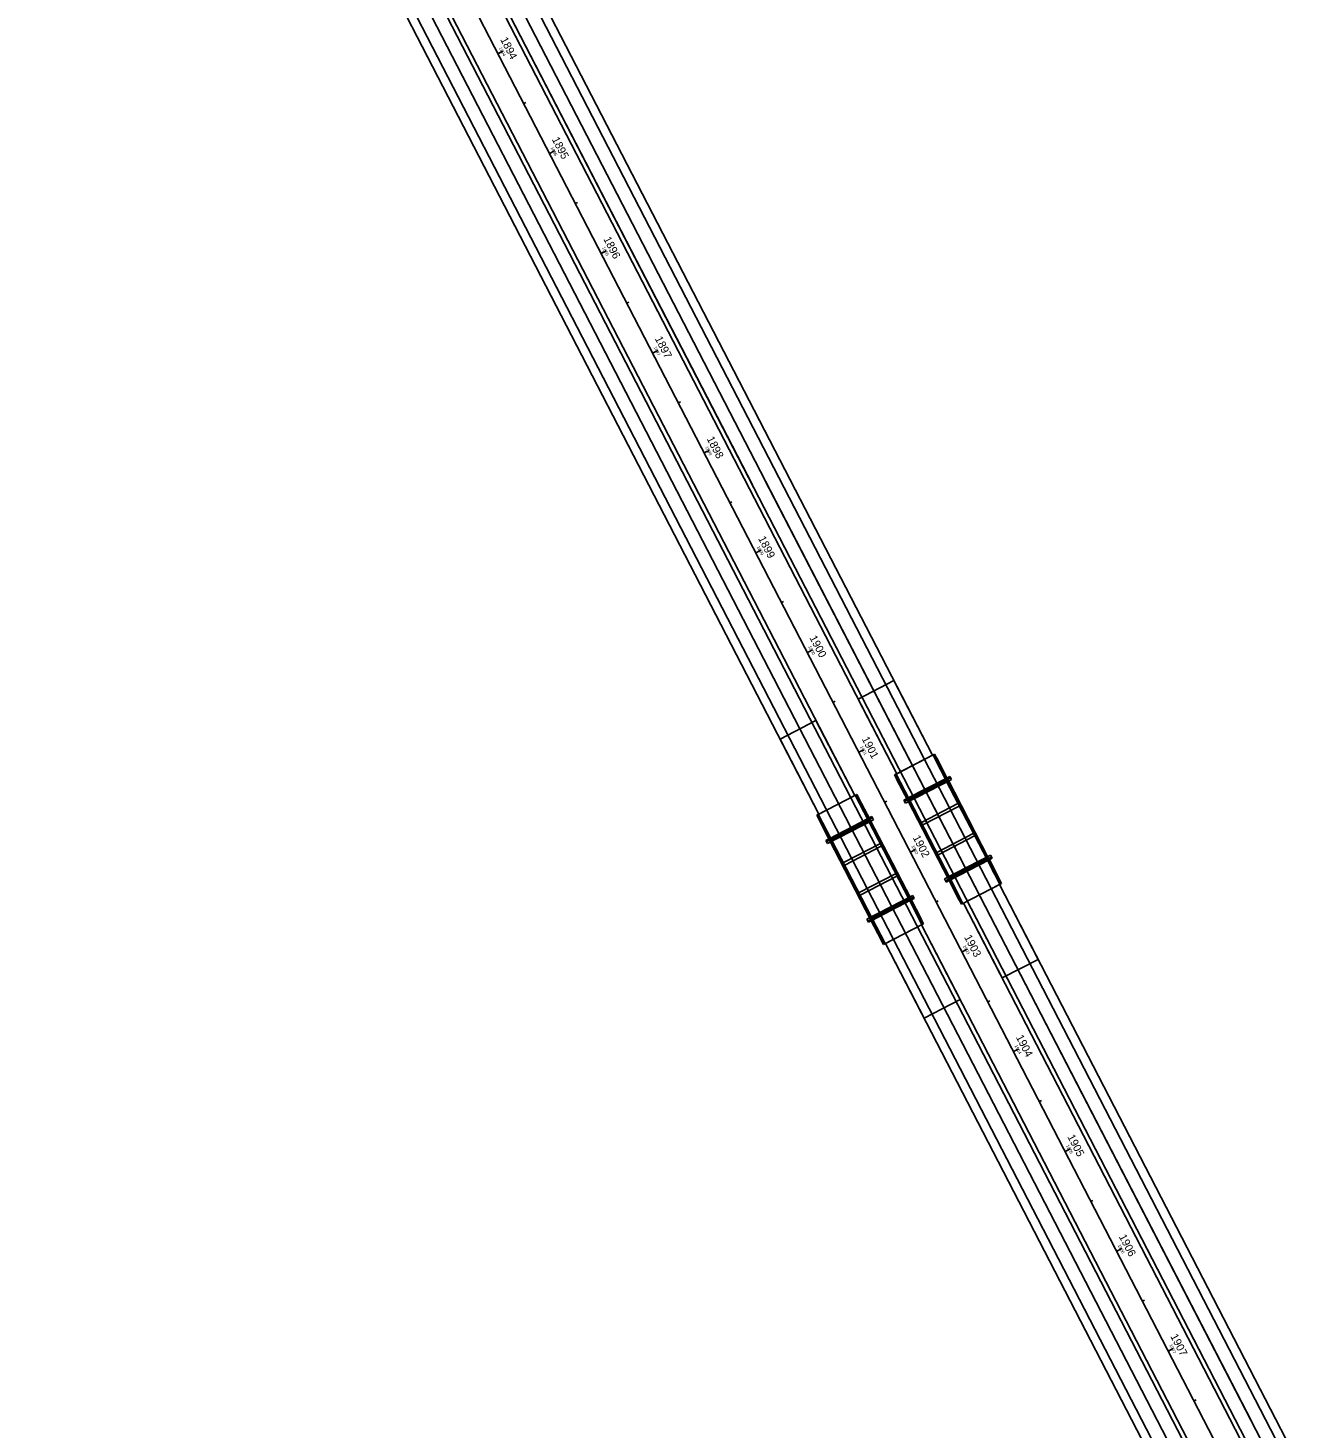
# Model space of a CAD drawing. Extents: x 8527 to 36635, y 12099 to 39012.
# Drawn here: x 24245 to 25376, y 26503 to 27749 of the extents above; entities that cross this region are included whole.
import ezdxf

# ---------------------------------------------------------------- set-up
doc = ezdxf.new("R2010")
doc.units = 0
for name, color, linetype in [('BR_P_Slab_Object', 7, 'Continuous'), ('BR_X_Rail_Object', 7, 'Continuous'), ('BR_X_Slab_Object', 7, 'Continuous'), ('BR_X_Sub_Hidden', 7, 'Continuous'), ('BR_X_Sub_Object', 7, 'Continuous'), ('DR_P_Inlet_Protection', 7, 'Continuous'), ('GE_X_CL_20', 7, 'Continuous'), ('GE_X_CL_50', 7, 'Continuous'), ('MT_P_Cells', 7, 'Continuous'), ('MT_P_Drums', 7, 'Continuous'), ('MT_P_Edge_Line', 7, 'Continuous'), ('MT_P_PCB', 7, 'Continuous'), ('MT_P_Temp_Road', 7, 'Continuous'), ('MT_P_Text', 7, 'Continuous'), ('RD_P_GR_Lt', 7, 'Continuous'), ('RD_P_GR_Rt', 7, 'Continuous'), ('SN_P_Signs', 7, 'Continuous')]:
    doc.layers.add(name, color=color, linetype=linetype)

msp = doc.modelspace()

# ---------------------------------------------------------------- linework, layer by layer
at = {"layer": 'BR_P_Slab_Object'}
for p, q in [((25063.6, 27080.5), (25100.1, 27009.9)), ((25028.1, 27062.2), (25064.6, 26991.5)), ((24994.3, 27044.7), (25030.8, 26974.1)), ((24958.8, 27026.4), (24995.3, 26955.7))]:
    msp.add_line(p, q, dxfattribs=at)
at = {"layer": 'BR_X_Rail_Object'}
for p, q in [((25051.1, 27102.2), (25052, 27102.6)), ((25017.7, 27084.9), (25016.8, 27084.5)), ((24981.8, 27066.4), (24982.7, 27066.8)), ((24948.4, 27049.1), (24947.5, 27048.7)), ((25110.5, 26987.1), (25111.4, 26987.6)), ((25077.1, 26969.9), (25076.2, 26969.4)), ((25041.2, 26951.3), (25042.1, 26951.8)), ((25007.8, 26934.1), (25006.9, 26933.6))]:
    msp.add_line(p, q, dxfattribs=at)
at = {"layer": 'BR_X_Slab_Object'}
for p, q in [((24958.8, 27026.4), (24994.3, 27044.7)), ((25064.6, 26991.5), (25100.1, 27009.9)), ((24995.3, 26955.7), (25030.8, 26974.1))]:
    msp.add_line(p, q, dxfattribs=at)
at = {"layer": 'BR_X_Sub_Hidden'}
for p, q in [((25063, 27081.6), (25027.5, 27063.3)), ((25063.3, 27081.2), (25027.7, 27062.8)), ((25040.4, 27042.1), (25072.8, 27058.8)), ((25041.6, 27039.9), (25074, 27056.6)), ((24958.2, 27027.5), (24993.7, 27045.8)), ((24958.4, 27027), (24994, 27045.4)), ((24971.1, 27006.3), (25003.5, 27023)), ((25054.2, 27015.4), (25086.6, 27032.2)), ((25055.3, 27013.2), (25087.8, 27030)), ((24972.3, 27004.1), (25004.7, 27020.8)), ((25100.4, 27009.2), (25064.9, 26990.9)), ((25100.7, 27008.8), (25065.1, 26990.4)), ((24984.9, 26979.6), (25017.3, 26996.4)), ((24986, 26977.4), (25018.5, 26994.2)), ((24995.6, 26955.1), (25031.1, 26973.4)), ((24995.8, 26954.6), (25031.4, 26973))]:
    msp.add_line(p, q, dxfattribs=at)
for centre, start, end in [((25073.4, 27057.7), 297.3208, 117.3208), ((25041, 27041), 117.3208, 297.3208), ((25004.1, 27021.9), 297.3208, 117.3208), ((25087.2, 27031.1), 297.3208, 117.3208), ((25054.8, 27014.3), 117.3208, 297.3208), ((24971.7, 27005.2), 117.3208, 297.3208), ((25017.9, 26995.3), 297.3208, 117.3208), ((24985.5, 26978.5), 117.3208, 297.3208)]:
    msp.add_arc(centre, 1.25, start, end, dxfattribs=at)
at = {"layer": 'BR_X_Sub_Object'}
for p, q in [((25067.1, 27080.3), (25026.2, 27059.2)), ((25063.7, 27079.2), (25029.1, 27061.3)), ((25063, 27081.6), (25065.7, 27083)), ((25063, 27081.6), (25063.6, 27080.5)), ((25063.2, 27080.3), (25063.7, 27079.2)), ((25063.6, 27080.5), (25066.3, 27081.9)), ((25065.7, 27083), (25067.1, 27080.3)), ((25027.5, 27063.3), (25024.8, 27061.9)), ((25024.8, 27061.9), (25026.2, 27059.2)), ((25028.1, 27062.2), (25025.4, 27060.8)), ((25027.5, 27063.3), (25028.1, 27062.2)), ((25028.5, 27062.4), (25029.1, 27061.3)), ((24993.7, 27045.8), (24996.4, 27047.2)), ((24996.4, 27047.2), (24997.8, 27044.5)), ((24956.9, 27023.4), (24997.8, 27044.5)), ((24959.8, 27025.5), (24994.4, 27043.4)), ((24993.7, 27045.8), (24994.3, 27044.7)), ((24993.9, 27044.5), (24994.4, 27043.4)), ((24994.3, 27044.7), (24997, 27046.1)), ((24958.2, 27027.5), (24955.5, 27026.1)), ((24955.5, 27026.1), (24956.9, 27023.4)), ((24958.8, 27026.4), (24956.1, 27025)), ((24958.2, 27027.5), (24958.8, 27026.4)), ((24959.2, 27026.6), (24959.8, 27025.5)), ((25102, 27012.8), (25061.1, 26991.7)), ((25099.1, 27010.8), (25064.4, 26992.9)), ((25099.7, 27009.7), (25099.1, 27010.8)), ((25100.1, 27009.9), (25102.8, 27011.3)), ((25100.7, 27008.8), (25100.1, 27009.9)), ((25100.7, 27008.8), (25103.3, 27010.2)), ((25103.3, 27010.2), (25102, 27012.8)), ((25062.5, 26989), (25061.1, 26991.7)), ((25064.6, 26991.5), (25061.9, 26990.2)), ((25065.1, 26990.4), (25062.5, 26989)), ((25065, 26991.8), (25064.4, 26992.9)), ((25065.1, 26990.4), (25064.6, 26991.5)), ((24991.8, 26955.9), (25032.7, 26977)), ((24995.1, 26957.1), (25029.8, 26975)), ((25030.4, 26973.9), (25029.8, 26975)), ((25030.8, 26974.1), (25033.5, 26975.5)), ((25031.4, 26973), (25030.8, 26974.1)), ((25031.4, 26973), (25034, 26974.4)), ((25034, 26974.4), (25032.7, 26977)), ((24993.2, 26953.2), (24991.8, 26955.9)), ((24995.3, 26955.7), (24992.6, 26954.4)), ((24995.8, 26954.6), (24993.2, 26953.2)), ((24995.7, 26956), (24995.1, 26957.1)), ((24995.8, 26954.6), (24995.3, 26955.7))]:
    msp.add_line(p, q, dxfattribs=at)
at = {"layer": 'DR_P_Inlet_Protection'}
msp.add_line((25334.4, 26508.5), (24900.6, 27348.1), dxfattribs=at)
at = {"layer": 'GE_X_CL_20'}
for p, q in [((24663.5, 27726.4), (24665.3, 27727.4)), ((24686.5, 27682), (24688.3, 27682.9)), ((24709.4, 27637.6), (24711.2, 27638.5)), ((24732.4, 27593.2), (24734.2, 27594.1)), ((24755.3, 27548.7), (24757.1, 27549.7)), ((24778.3, 27504.3), (24780.1, 27505.2)), ((24801.2, 27459.9), (24803, 27460.8)), ((24824.2, 27415.5), (24825.9, 27416.4)), ((24847.1, 27371.1), (24848.9, 27372)), ((24870.1, 27326.6), (24871.8, 27327.5)), ((24893, 27282.2), (24894.8, 27283.1)), ((24916, 27237.8), (24917.7, 27238.7)), ((24938.9, 27193.4), (24940.7, 27194.3)), ((24961.9, 27148.9), (24963.6, 27149.9)), ((24984.8, 27104.5), (24986.6, 27105.4)), ((25007.8, 27060.1), (25009.5, 27061)), ((25030.7, 27015.7), (25032.5, 27016.6)), ((25053.7, 26971.3), (25055.4, 26972.2)), ((25076.6, 26926.8), (25078.4, 26927.7)), ((25099.6, 26882.4), (25101.3, 26883.3)), ((25122.5, 26838), (25124.3, 26838.9)), ((25145.5, 26793.6), (25147.2, 26794.5)), ((25168.4, 26749.1), (25170.2, 26750.1)), ((25191.3, 26704.7), (25193.1, 26705.6)), ((25214.3, 26660.3), (25216.1, 26661.2)), ((25237.2, 26615.9), (25239, 26616.8)), ((25260.2, 26571.4), (25262, 26572.4)), ((25283.1, 26527), (25284.9, 26527.9))]:
    msp.add_line(p, q, dxfattribs=at)
at = {"layer": 'GE_X_CL_50'}
msp.add_line((24318.1, 28449.5), (24890, 27342.5), dxfattribs=at)
at = {"layer": 'MT_P_Cells'}
for p, q in [((25050.8, 27102), (25052.1, 27102.7)), ((25050.8, 27102), (25062.2, 27079.9)), ((25051.3, 27102.3), (25051.8, 27100.9)), ((25051.8, 27100.9), (25052.9, 27098.6)), ((25052.1, 27102.7), (25063.6, 27080.6)), ((25052.6, 27098.5), (25054.1, 27099.3)), ((25052.9, 27098.6), (25057.2, 27089.6)), ((25052.9, 27098.6), (25057.8, 27089.9)), ((25054.1, 27099.3), (25063.7, 27080.7)), ((25017.9, 27085.1), (25016.6, 27084.4)), ((25016.6, 27084.4), (25028, 27062.2)), ((25017.5, 27084.8), (25018.4, 27083.6)), ((25017.9, 27085.1), (25029.4, 27062.9)), ((25057.2, 27089.6), (25058.6, 27090.3)), ((25057.8, 27089.9), (25062.8, 27080.2)), ((25019.8, 27081.5), (25018.3, 27080.7)), ((25018.3, 27080.7), (25027.9, 27062.2)), ((25018.4, 27083.6), (25019.5, 27081.4)), ((25019.5, 27081.4), (25024.4, 27072.6)), ((25019.5, 27081.4), (25023.8, 27072.3)), ((25024.4, 27072.6), (25023, 27071.9)), ((25023.8, 27072.3), (25028.8, 27062.6)), ((25062.2, 27079.9), (25063.7, 27080.7)), ((24981.5, 27066.3), (24982.8, 27066.9)), ((24981.5, 27066.3), (24992.9, 27044.1)), ((24982, 27066.5), (24982.5, 27065.1)), ((24982.5, 27065.1), (24983.6, 27062.8)), ((24982.8, 27066.9), (24994.3, 27044.8)), ((24983.3, 27062.7), (24984.8, 27063.5)), ((24983.6, 27062.8), (24987.9, 27053.8)), ((24983.6, 27062.8), (24988.5, 27054.1)), ((24984.8, 27063.5), (24994.4, 27044.9)), ((25029.4, 27062.9), (25027.9, 27062.2)), ((24948.6, 27049.3), (24947.3, 27048.6)), ((24947.3, 27048.6), (24958.7, 27026.4)), ((24948.2, 27049), (24949.1, 27047.8)), ((24948.6, 27049.3), (24960.1, 27027.1)), ((24949.1, 27047.8), (24950.2, 27045.6)), ((24987.9, 27053.8), (24989.3, 27054.5)), ((24988.5, 27054.1), (24993.5, 27044.4)), ((24950.5, 27045.7), (24949, 27044.9)), ((24949, 27044.9), (24958.6, 27026.4)), ((24950.2, 27045.6), (24955.1, 27036.8)), ((24950.2, 27045.6), (24954.5, 27036.5)), ((24955.1, 27036.8), (24953.7, 27036.1)), ((24954.5, 27036.5), (24959.5, 27026.8)), ((24992.9, 27044.1), (24994.4, 27044.9)), ((24960.1, 27027.1), (24958.6, 27026.4)), ((25098.8, 27009.1), (25100.3, 27009.9)), ((25111.6, 26987.7), (25100.1, 27009.8)), ((25109.9, 26991.3), (25100.3, 27009.9)), ((25110.2, 26987), (25098.8, 27009.1)), ((25104.4, 26999.7), (25099.4, 27009.4)), ((25103.8, 26999.4), (25105.1, 27000.1)), ((25108.7, 26990.7), (25103.8, 26999.4)), ((25108.7, 26990.7), (25104.4, 26999.7)), ((25065.9, 26992.2), (25064.5, 26991.4)), ((25074.1, 26972.8), (25064.5, 26991.4)), ((25076, 26969.3), (25064.6, 26991.5)), ((25070.4, 26982.1), (25065.3, 26991.8)), ((25077.4, 26970), (25065.9, 26992.2)), ((25108.4, 26990.5), (25109.9, 26991.3)), ((25109.8, 26988.5), (25108.7, 26990.7)), ((25110.7, 26987.2), (25109.8, 26988.5)), ((25110.2, 26987), (25111.6, 26987.7)), ((25029.5, 26973.3), (25031, 26974.1)), ((25040.9, 26951.2), (25029.5, 26973.3)), ((25035.1, 26963.9), (25030.1, 26973.6)), ((25042.3, 26951.9), (25030.8, 26974)), ((25040.6, 26955.5), (25031, 26974.1)), ((25070.9, 26982.5), (25069.6, 26981.8)), ((25075.3, 26973.4), (25070.4, 26982.1)), ((25075.3, 26973.4), (25070.9, 26982.5)), ((25075.5, 26973.6), (25074.1, 26972.8)), ((25076.4, 26971.2), (25075.3, 26973.4)), ((25034.5, 26963.6), (25035.8, 26964.3)), ((25039.4, 26954.9), (25034.5, 26963.6)), ((25039.4, 26954.9), (25035.1, 26963.9)), ((25077.4, 26970), (25076, 26969.3)), ((25076.9, 26969.8), (25076.4, 26971.2)), ((24996.6, 26956.4), (24995.2, 26955.6)), ((25004.8, 26937), (24995.2, 26955.6)), ((25006.7, 26933.5), (24995.3, 26955.7)), ((25001.1, 26946.3), (24996, 26956)), ((25008.1, 26934.2), (24996.6, 26956.4)), ((25039.1, 26954.8), (25040.6, 26955.5)), ((25041.4, 26951.4), (25040.5, 26952.7)), ((25040.9, 26951.2), (25042.3, 26951.9)), ((25001.6, 26946.7), (25000.3, 26946)), ((25006, 26937.6), (25001.1, 26946.3)), ((25006, 26937.6), (25001.6, 26946.7)), ((25006.2, 26937.8), (25004.8, 26937)), ((25007.1, 26935.4), (25006, 26937.6)), ((25007.6, 26934), (25007.1, 26935.4)), ((25008.1, 26934.2), (25006.7, 26933.5))]:
    msp.add_line(p, q, dxfattribs=at)
at = {"layer": 'MT_P_Drums'}
for p, q in [((24984, 27151.9), (25015.9, 27168.5)), ((24914.7, 27116.1), (24946.6, 27132.7)), ((25112.2, 26903.6), (25144.2, 26920.1)), ((25042.9, 26867.8), (25074.9, 26884.3))]:
    msp.add_line(p, q, dxfattribs=at)
for points in [[(24984, 27151.9), (25018.4, 27085.3), (25050.4, 27101.8), (25015.9, 27168.5)], [(24914.7, 27116.1), (24949.1, 27049.5), (24981.1, 27066), (24946.6, 27132.7)], [(25112.2, 26903.6), (25077.8, 26970.2), (25109.8, 26986.8), (25144.2, 26920.1)], [(25042.9, 26867.8), (25008.5, 26934.4), (25040.5, 26951), (25074.9, 26884.3)]]:
    msp.add_lwpolyline(points, close=True, dxfattribs=at)
at = {"layer": 'MT_P_Edge_Line'}
for p, q in [((24346.6, 28464.2), (25050.4, 27101.8)), ((24314.6, 28447.7), (25018.4, 27085.3)), ((24277.3, 28428.4), (24981.1, 27066)), ((24245.3, 28411.9), (24949.1, 27049.5)), ((25109.8, 26986.8), (26773.4, 23766.4)), ((25077.8, 26970.2), (26741.4, 23749.9)), ((25040.5, 26951), (26704.1, 23730.6)), ((25008.5, 26934.4), (26672.1, 23714.1))]:
    msp.add_line(p, q, dxfattribs=at)
at = {"layer": 'MT_P_PCB'}
for p, q in [((24328.8, 28455), (26755.6, 23757.3)), ((24263, 28421), (26689.9, 23723.3))]:
    msp.add_line(p, q, dxfattribs=at)
at = {"layer": 'MT_P_Temp_Road'}
for p, q in [((24339.5, 28460.5), (26766.3, 23762.8)), ((24318.1, 28449.5), (26745, 23751.8)), ((24273.7, 28426.6), (26700.6, 23728.8)), ((24252.4, 28415.5), (26679.2, 23717.8))]:
    msp.add_line(p, q, dxfattribs=at)
at = {"layer": 'MT_P_Text'}
for p, q in [((24295.9, 28438), (26722.8, 23740.3)), ((24663.5, 27726.4), (24668, 27728.7)), ((24709.4, 27637.6), (24713.9, 27639.9)), ((24755.3, 27548.7), (24759.8, 27551)), ((24801.2, 27459.9), (24805.7, 27462.2)), ((24847.1, 27371.1), (24851.6, 27373.3)), ((24893, 27282.2), (24897.5, 27284.5)), ((24938.9, 27193.4), (24943.4, 27195.7)), ((24984.8, 27104.5), (24989.3, 27106.8)), ((25030.7, 27015.7), (25035.2, 27018)), ((25076.6, 26926.8), (25081, 26929.1)), ((25122.5, 26838), (25126.9, 26840.3)), ((25168.4, 26749.1), (25172.8, 26751.4)), ((25214.3, 26660.3), (25218.7, 26662.6)), ((25260.2, 26571.4), (25264.6, 26573.7))]:
    msp.add_line(p, q, dxfattribs=at)
at = {"layer": 'RD_P_GR_Lt'}
for p, q in [((25062.3, 27079.8), (25063.8, 27080.6)), ((25062.3, 27079.8), (25098.8, 27009.2)), ((25062.9, 27080.1), (25099.4, 27009.5)), ((25063.8, 27080.6), (25100.2, 27010)), ((25064, 27079.9), (25099.8, 27010.6)), ((25029.4, 27062.9), (25027.9, 27062.1)), ((25027.9, 27062.1), (25064.4, 26991.5)), ((25028.4, 27061.5), (25064.2, 26992.2)), ((25028.8, 27062.6), (25065.3, 26991.9)), ((25029.4, 27062.9), (25065.9, 26992.2)), ((24993, 27044), (24994.5, 27044.8)), ((24993, 27044), (25029.5, 26973.4)), ((24993.6, 27044.3), (25030.1, 26973.7)), ((24994.5, 27044.8), (25031, 26974.2)), ((24994.7, 27044.1), (25030.5, 26974.8)), ((24960.1, 27027.1), (24958.6, 27026.3)), ((24958.6, 27026.3), (24995.1, 26955.7)), ((24959.1, 27025.7), (24994.9, 26956.4)), ((24959.5, 27026.8), (24996, 26956.1)), ((24960.1, 27027.1), (24996.6, 26956.4)), ((25098.8, 27009.2), (25100.2, 27010)), ((25065.9, 26992.2), (25064.4, 26991.5)), ((25029.5, 26973.4), (25031, 26974.2)), ((24996.6, 26956.4), (24995.1, 26955.7))]:
    msp.add_line(p, q, dxfattribs=at)
at = {"layer": 'RD_P_GR_Rt'}
for p, q in [((25052.1, 27102.7), (25016.6, 27084.4)), ((25063.6, 27080.5), (25028.1, 27062.2)), ((24982.8, 27066.9), (24947.3, 27048.6)), ((24994.3, 27044.7), (24958.8, 27026.4)), ((25100.1, 27009.9), (25064.6, 26991.5)), ((25111.6, 26987.7), (25076, 26969.3)), ((24995.3, 26955.7), (25030.8, 26974.1)), ((25006.7, 26933.5), (25042.3, 26951.9)), ((25039.4, 26954.9), (25040.5, 26952.7))]:
    msp.add_line(p, q, dxfattribs=at)
at = {"layer": 'SN_P_Signs'}
for p, q in [((25052.1, 27102.7), (25063.6, 27080.5)), ((25016.6, 27084.4), (25028.1, 27062.2)), ((25063.6, 27080.5), (25028.1, 27062.2)), ((24982.8, 27066.9), (24994.3, 27044.7)), ((24947.3, 27048.6), (24958.8, 27026.4)), ((25111.6, 26987.7), (25100.1, 27009.9)), ((25076, 26969.3), (25064.6, 26991.5)), ((25042.3, 26951.9), (25030.8, 26974.1)), ((25006.7, 26933.5), (24995.3, 26955.7))]:
    msp.add_line(p, q, dxfattribs=at)

# ---------------------------------------------------------------- texts
at = {"layer": 'GE_X_CL_20'}
for s, p in [('1894', (24664.3, 27731.5)), ('1895', (24710.2, 27642.7)), ('1896', (24756.1, 27553.8)), ('1897', (24801.9, 27465)), ('1898', (24847.9, 27376.1)), ('1899', (24893.8, 27287.3)), ('1900', (24939.6, 27198.6)), ('1901', (24985.7, 27109.3)), ('1902', (25031.4, 27020.9)), ('1903', (25077.3, 26932)), ('1904', (25123.2, 26843.2)), ('1905', (25169.1, 26754.3)), ('1906', (25215, 26665.5)), ('1907', (25260.9, 26576.7))]:
    msp.add_text(s, height=2.8, rotation=297.3208, dxfattribs=at).set_placement(p)
at = {"layer": 'MT_P_Text'}
for s, p in [('1894', (24665.4, 27739.1)), ('1895', (24711.3, 27650.3)), ('1896', (24757.2, 27561.5)), ('1897', (24803, 27472.8)), ('1898', (24849.1, 27383.7)), ('1899', (24894.9, 27294.9)), ('1900', (24940.6, 27206.5)), ('1901', (24987.1, 27116.5)), ('1902', (25032.5, 27028.6)), ('1903', (25078.3, 26939.9)), ('1904', (25124.3, 26850.9)), ('1905', (25170.1, 26762.2)), ('1906', (25216, 26673.3)), ('1907', (25261.8, 26584.6))]:
    msp.add_text(s, height=7, rotation=297.3208, dxfattribs=at).set_placement(p)

doc.saveas('drawing.dxf')
